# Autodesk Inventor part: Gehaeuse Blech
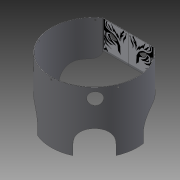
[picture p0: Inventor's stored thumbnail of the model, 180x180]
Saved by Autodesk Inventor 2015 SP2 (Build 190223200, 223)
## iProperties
Created: 2015-11
Part Number: Gehaeuse Blech
Material: Allgemein
Document SubType Name: Blech
Designer: ryll
Density: 1 g/cm^3
Sheet Metal Rule: Standard
Appearance: Vorgabe
Sheet Metal Width: 124,800 mm
Sheet Metal Length: 541,718 mm
Sheet Metal Area: 67606,352 mm^2
Flat Pattern Width: 12.48 cm
Flat Pattern Length: 54.1718 cm
Flat Pattern Area: 676.064 cm^2
Author: ryll
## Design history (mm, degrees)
node "Konturlasche2"
  sketch "Skizze7"
    geometry: L1 (-52.333, 69.5)-(-0.001, 69.5); L2 (52.333, 69.5)-(0.001, 69.5); L3 (0, 100.8)-(0, -118.3) reference; A1 r 87 centre (0, 0) between (-52.333, 69.5) and (52.333, 69.5); 1 further point
    constraints: 4 end point, 2 horizontal, 2 point on circle, 1 centre point, 1 coincident, 1 collinear, 1 symmetric about line
    dimensions: "d52" = 174 diameter of A1; "d53" = 69.5 distance from line of point (0, 0) L1; "d54" = 0.001 distance of L2.end L1.end
node "Abwickeln2"
feature "Ausklinkung3" dims "d69" = 1 (= Stärke), "d70" = 0
node "Zurückfaltung2"
node "Definition der A-Seite"
sketch "Skizze18"
  geometry: L1 (52.509, 0.265)-(-51.64, 0.265); L2 (-51.64, 0.265)-(-51.64, 54.169); L3 (-51.64, 54.169)-(52.509, 54.169); L4 (52.509, 54.169)-(52.509, 0.265); 1 further point; 1 other entity
  constraints: 2 other
feature "Aufkleber10" sketch "Skizze18"
sketch "Skizze19"
  geometry: L1 (103.602, 0.401)-(-0.547, 0.401); L2 (-0.547, 0.401)-(-0.547, 54.306); L3 (-0.547, 54.306)-(103.602, 54.306); L4 (103.602, 54.306)-(103.602, 0.401); 1 further point; 1 other entity
  constraints: 2 other
feature "Aufkleber11" sketch "Skizze19"
sketch "Skizze22"
  geometry: L1 (-53.207, 0)-(-53.207, 61.318) reference; L2 (51.997, 0)-(-52.152, 0); L3 (-52.152, 0)-(-52.152, 53.909); L4 (-52.152, 53.909)-(51.997, 53.909); L5 (51.997, 53.909)-(51.997, 0); L6 (0, 58)-(0, 0) reference; L7 (51.997, 0)-(0, 0) reference; L8 (51.997, 0)-(51.997, 58) reference; L9 (51.997, 0)-(0, 0) reference; L10 (51.997, 0)-(51.997, 58) reference; L11 (51.997, 58)-(0, 58) reference; 3 further points; 1 other entity
  constraints: 2 collinear, 2 other
feature "Aufkleber14" sketch "Skizze22"
node "Volumenkörper1"
feature "Grobblech6" dims "d58" = 1 (= BreiteBiegungsfreistellung), "d59" = 0.5 (= TiefeBiegungsfreistellung), "d60" = 2 (= MinimalRest), "d61" = 1 (= Biegeradius), "d62" = 124.8, "d63" = 1 (= Biegeradius), "d64" = 1.5, "d65" = 4 (= GrößeEckenfreistellung), "d66" = 1 (= Abstandsgröße), "d67" = 1 (= JacobiRadiusGröße), "Stärke" = 1, "AbstandVerbindung" = 0.01
feature "Biegung4" dims "d58" = 1 (= BreiteBiegungsfreistellung), "d59" = 0.5 (= TiefeBiegungsfreistellung), "d60" = 2 (= MinimalRest), "d61" = 1 (= Biegeradius), "d63" = 1 (= Biegeradius), "d64" = 1.5, "Stärke" = 1, "AbstandVerbindung" = 0.01
feature "Ecke2" dims "d64" = 1.5, "d65" = 4 (= GrößeEckenfreistellung), "d66" = 1 (= Abstandsgröße), "d67" = 1 (= JacobiRadiusGröße)
sketch "Skizze9"
  geometry: L1 (488.785, 124.8)-(488.785, 0) reference; L2 (-52.932, 124.8)-(-52.932, 0) reference; L3 (-0.935, 0)-(-0.935, 124.8) reference; L4 (436.788, 0)-(436.788, 124.8) reference; L5 (436.788, 124.8)-(436.788, 0) reference; L6 (436.788, 58)-(488.785, 58); L7 (488.785, 58)-(488.785, 124.8); L8 (488.785, 0)-(436.788, 0) reference; L9 (-0.935, 58)-(-52.932, 58); L10 (-52.932, 58)-(-52.932, 124.8); L11 (435.853, 124.8)-(0, 124.8) reference; L12 (435.853, 0)-(0, 0) reference; L13 (435.853, 124.8)-(0, 124.8) reference; L14 (217.927, 124.8)-(217.927, 0); L15 (0, 0)-(435.853, 0) reference; L16 (254.927, 124.8)-(318.927, 124.8); L17 (318.927, 124.8)-(318.927, 104.8); L18 (254.927, 104.8)-(254.927, 124.8); L19 (368.927, 104.8)-(368.927, 124.8); L20 (180.927, 124.8)-(116.927, 124.8); L21 (116.927, 124.8)-(116.927, 104.8); L22 (180.927, 104.8)-(180.927, 124.8); L23 (66.927, 104.8)-(66.927, 124.8); L24 (400.927, 72.8)-(419.075, 72.8); L25 (400.927, 104.8)-(34.927, 104.8); L26 (34.927, 72.8)-(16.778, 72.8); L27 (-0.935, 124.8)-(-0.935, 0) reference; L28 (488.785, 124.8)-(368.927, 124.8); L29 (-52.932, 124.8)-(66.927, 124.8); L30 (287.927, 20)-(147.927, 20); L31 (484.785, 4.5)-(-48.932, 4.5); C1 r 12.5 at (287.927, 20); C2 r 12.5 at (147.927, 20); C3 r 1.6 at (484.785, 4.5); C4 r 1.6 at (-48.932, 4.5); C5 r 1.6 at (425.427, 4.5); C6 r 1.6 at (321.677, 4.5); C7 r 1.6 at (217.927, 4.5); C8 r 1.6 at (10.427, 4.5); C9 r 1.6 at (114.177, 4.5); A1 r 32 centre (286.927, 104.8) between (254.927, 104.8) and (318.927, 104.8); A2 r 32 centre (148.927, 104.8) between (116.927, 104.8) and (180.927, 104.8); A3 r 32 centre (400.927, 104.8) between (368.927, 104.8) and (400.927, 72.8); A4 r 32 centre (34.927, 104.8) between (34.927, 72.8) and (66.927, 104.8); A5 r 18 centre (419.075, 54.8) between (436.788, 58) and (419.075, 72.8); A6 r 18 centre (16.778, 54.8) between (16.778, 72.8) and (-0.935, 58); A7 r 22.532 centre (-12.523, 40.266) between (-29.537, 25.493) and (-16.285, 18.05); A8 r 4.823 centre (-25.563, 22.759) between (-26.915, 27.389) and (-29.537, 25.493); A9 r 10.252 centre (-26.455, 19.352) between (-16.285, 18.05) and (-19.311, 26.705); A10 r 10.457 centre (-23.984, 17.35) between (-19.311, 26.705) and (-26.915, 27.389); A11 r 10.457 centre (459.838, 17.35) between (462.768, 27.389) and (455.164, 26.705); A12 r 10.252 centre (462.308, 19.352) between (455.164, 26.705) and (452.139, 18.05); A13 r 22.532 centre (448.377, 40.266) between (452.139, 18.05) and (465.39, 25.493); A14 r 4.823 centre (461.416, 22.759) between (465.39, 25.493) and (462.768, 27.389); 2 further points
  constraints: 40 end point, 29 point on circle, 23 centre point, 13 point on line, 12 symmetric about line, 11 tangent, 7 equal radius, 6 collinear, 6 horizontal, 4 midpoint, 3 coincident, 2 parallel, 2 perpendicular, 6 other
  dimensions: "d68" = 58 distance between parallel lines of L8 L6; "d71" = 64 distance between parallel lines of L18 L17; "d73" = 64 distance between parallel lines of L22 L21 (= d71); "d75" = 37 distance between parallel lines of L14 L18; "d76" = 50 distance between parallel lines of L19 L17; "d77" = 20 distance between parallel lines of L11 L25; "d79" = 18 radius of A5; "d80" = 18 radius of A6; "d81" = 25 diameter of C1; "d82" = 20 distance between parallel lines of L12 L30; "d83" = 140 distance of L30.start L30.end; "d87" = 3.2 diameter of C3; "d88" = 4.5 distance between parallel lines of L15 L31; "d90" = 415 distance of C8.centre C5.centre; "d91" = 207.5 distance of C9.centre C6.centre; "d272" = 4 distance from line of L1 L31.start
node "Bild16"
node "Bild17"
node "Bild21"
node "Projizierte Kontur6"
feature "Definition1"
other parameters: "KFaktor" = 4.4, "Biegeradius" = 1 (= Stärke), "BreiteBiegungsfreistellung" = 1 (= Stärke), "TiefeBiegungsfreistellung" = 0.5 (= 0.5 x Stärke), "GrößeEckenfreistellung" = 4 (= 4 x Stärke), "MinimalRest" = 2 (= 2 x Stärke), "Übergangsradius" = 1 (= Biegeradius), "JacobiRadiusGröße" = 1 (= Stärke), "Abstandsgröße" = 1 (= Stärke), "d4" = 1 (= Biegeradius), "d57" = 1 (= Biegeradius), "Abstandsgröße" = 1, "Biegeradius" = 1, "BreiteBiegungsfreistellung" = 1, "GrößeEckenfreistellung" = 4, "JacobiRadiusGröße" = 1, "MinimalRest" = 2, "Stärke" = 1, "TiefeBiegungsfreistellung" = 0.5, "Übergangsradius" = 1
